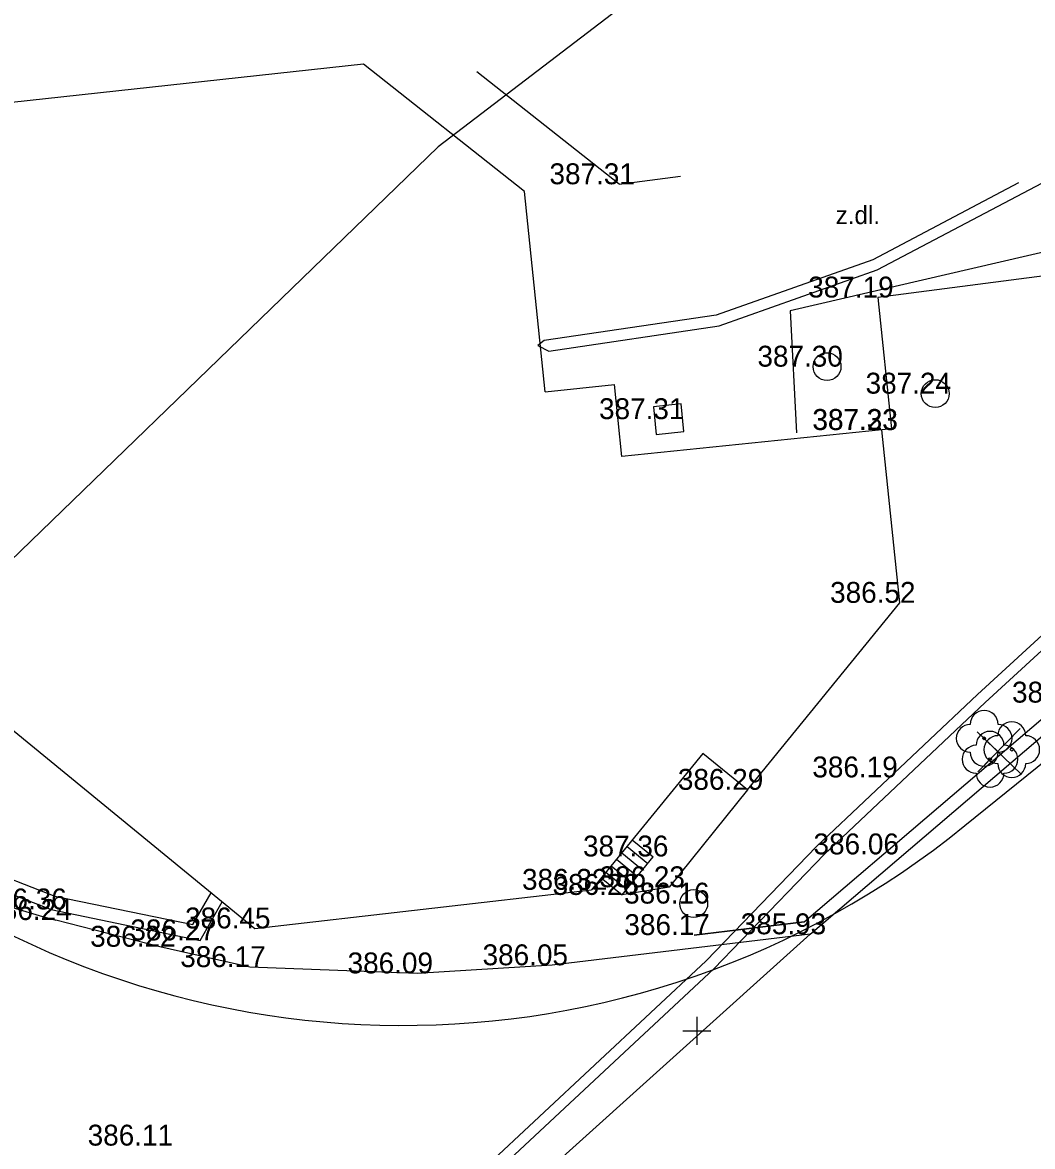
# Model space of a CAD drawing. Extents: x -438233 to -437334, y -1133133 to -1132623.
# Drawn here: x -438124.22 to -438087.94, y -1132954.16 to -1132913.79 of the extents above; entities that cross this region are included whole.
import ezdxf

# ---------------------------------------------------------------- set-up
doc = ezdxf.new("R2010")
doc.units = 0
for name, color, linetype in [('Vrstva 1', 7, 'Continuous'), ('Vrstva 10', 7, 'Continuous'), ('Vrstva 11', 7, 'Continuous'), ('Vrstva 22', 7, 'Continuous'), ('Vrstva 26', 7, 'Continuous'), ('Vrstva 27', 7, 'Continuous'), ('Vrstva 3', 7, 'Continuous'), ('Vrstva 40', 7, 'Continuous'), ('Vrstva 5', 7, 'Continuous'), ('Vrstva 52', 7, 'Continuous'), ('Vrstva 54', 7, 'Continuous'), ('Vrstva 55', 7, 'Continuous'), ('Vrstva 61', 7, 'Continuous'), ('Vrstva 7', 7, 'Continuous'), ('Vrstva 9', 7, 'Continuous')]:
    doc.layers.add(name, color=color, linetype=linetype)

msp = doc.modelspace()

# ---------------------------------------------------------------- linework, layer by layer
at = {"layer": 'Vrstva 1'}
for p, q in [((-438111.968, -1132915.287), (-438111.968, -1132915.287)), ((-438106.192, -1132919.855), (-438106.192, -1132919.855)), ((-438102.793, -1132919.6), (-438102.793, -1132919.6)), ((-438093.499, -1132923.668), (-438093.499, -1132923.668)), ((-438095.324, -1132926.15), (-438095.324, -1132926.15)), ((-438102.958, -1132926.794), (-438102.958, -1132926.794)), ((-438091.439, -1132927.119), (-438091.439, -1132927.119)), ((-438101.013, -1132928.035), (-438101.013, -1132928.035)), ((-438093.353, -1132928.422), (-438093.353, -1132928.422)), ((-438093.344, -1132928.427), (-438093.344, -1132928.427)), ((-438090.373, -1132942.634), (-438074.748, -1132930.004)), ((-438092.714, -1132934.632), (-438092.714, -1132934.632)), ((-438093.352, -1132940.901), (-438093.352, -1132940.901)), ((-438098.181, -1132941.346), (-438098.181, -1132941.346)), ((-438101.588, -1132943.74), (-438101.588, -1132943.74)), ((-438093.309, -1132943.665), (-438093.309, -1132943.665)), ((-438103.779, -1132944.937), (-438103.779, -1132944.937)), ((-438100.997, -1132944.845), (-438100.997, -1132944.845)), ((-438102.682, -1132945.121), (-438102.682, -1132945.121)), ((-438123.197, -1132945.641), (-438123.197, -1132945.641)), ((-438100.113, -1132945.432), (-438100.113, -1132945.432)), ((-438123.021, -1132946.022), (-438123.021, -1132946.022)), ((-438115.881, -1132946.325), (-438115.881, -1132946.325)), ((-438100.102, -1132946.562), (-438100.102, -1132946.562)), ((-438095.924, -1132946.534), (-438095.924, -1132946.534)), ((-438119.29, -1132946.982), (-438119.29, -1132946.982)), ((-438117.845, -1132946.752), (-438117.845, -1132946.752)), ((-438116.055, -1132947.713), (-438116.055, -1132947.713)), ((-438105.196, -1132947.647), (-438105.196, -1132947.647)), ((-438110.044, -1132947.938), (-438110.044, -1132947.938)), ((-438119.38, -1132954.123), (-438119.38, -1132954.123))]:
    msp.add_line(p, q, dxfattribs=at)
msp.add_arc((-438110.563, -1132917.807), 32, 230.3365, 309.1186, dxfattribs=at)
at = {"layer": 'Vrstva 10'}
msp.add_line((-438095.924, -1132946.534), (-438114.084, -1132962.853), dxfattribs=at)
for points in [[(-438095.924, -1132946.534), (-438086.179, -1132938.215), (-438074.983, -1132928.454)], [(-438095.924, -1132946.534), (-438105.196, -1132947.647), (-438110.044, -1132947.938), (-438116.055, -1132947.713), (-438119.29, -1132946.982), (-438123.021, -1132946.022)]]:
    msp.add_lwpolyline(points, dxfattribs=at)
msp.add_arc((-438115.759, -1132917.821), 29.121, 239.8641, 255.5591, dxfattribs=at)
at = {"layer": 'Vrstva 11'}
for p, q in [((-438102.508, -1132943.378), (-438101.759, -1132943.988)), ((-438102.319, -1132943.145), (-438101.57, -1132943.755)), ((-438102.698, -1132943.61), (-438101.949, -1132944.22)), ((-438103.077, -1132944.075), (-438102.328, -1132944.685)), ((-438102.887, -1132943.843), (-438102.138, -1132944.453)), ((-438103.431, -1132944.511), (-438102.682, -1132945.121)), ((-438103.266, -1132944.308), (-438102.517, -1132944.918))]:
    msp.add_line(p, q, dxfattribs=at)
for points in [[(-438102.793, -1132919.6), (-438107.901, -1132915.561)], [(-438102.793, -1132919.6), (-438100.584, -1132919.31)], [(-438080.604, -1132921.986), (-438093.499, -1132923.668), (-438093.013, -1132928.387), (-438093.353, -1132928.422)], [(-438098.181, -1132941.346), (-438100.997, -1132944.845), (-438102.682, -1132945.121)], [(-438102.682, -1132945.121), (-438101.57, -1132943.755)]]:
    msp.add_lwpolyline(points, dxfattribs=at)
at = {"layer": 'Vrstva 22'}
for centre in [(-438089.68, -1132939.498), (-438088.688, -1132939.904), (-438089.469, -1132940.248)]:
    msp.add_circle(centre, 0.05, dxfattribs=at)
for centre, start, end in [((-438089.68, -1132938.998), 0, 180), ((-438088.688, -1132939.404), 0, 180), ((-438090.18, -1132939.498), 90, 270), ((-438089.469, -1132939.748), 0, 180), ((-438089.18, -1132939.498), 270, 90), ((-438089.969, -1132940.248), 90, 270), ((-438089.188, -1132939.904), 90, 270), ((-438088.969, -1132940.248), 270, 90), ((-438088.188, -1132939.904), 270, 90), ((-438089.68, -1132939.998), 180, 0), ((-438088.688, -1132940.404), 180, 0), ((-438089.469, -1132940.748), 180, 0)]:
    msp.add_arc(centre, 0.5, start, end, dxfattribs=at)
at = {"layer": 'Vrstva 26'}
msp.add_lwpolyline([(-438100.567, -1132927.486), (-438101.562, -1132927.589), (-438101.459, -1132928.584), (-438100.464, -1132928.481)], close=True, dxfattribs=at)
at = {"layer": 'Vrstva 27'}
for centre in [(-438095.324, -1132926.15), (-438091.439, -1132927.119), (-438100.113, -1132945.432)]:
    msp.add_circle(centre, 0.5, dxfattribs=at)
at = {"layer": 'Vrstva 40'}
msp.add_lwpolyline([(-438088.386, -1132939.139), (-438089.906, -1132940.705), (-438089.195, -1132939.972), (-438089.928, -1132939.261), (-438088.356, -1132940.787)], dxfattribs=at)
at = {"layer": 'Vrstva 5'}
for p, q in [((-438105.451, -1132927.051), (-438106.192, -1132919.855)), ((-438105.451, -1132927.051), (-438102.958, -1132926.794)), ((-438102.691, -1132929.383), (-438102.958, -1132926.794)), ((-438093.353, -1132928.422), (-438102.691, -1132929.383)), ((-438092.714, -1132934.632), (-438093.353, -1132928.422)), ((-438098.181, -1132941.346), (-438092.714, -1132934.632)), ((-438125.927, -1132938.095), (-438115.881, -1132946.325)), ((-438099.789, -1132940.037), (-438103.778, -1132944.938)), ((-438098.181, -1132941.346), (-438099.789, -1132940.037)), ((-438115.881, -1132946.325), (-438103.779, -1132944.937))]:
    msp.add_line(p, q, dxfattribs=at)
for points in [[(-438111.968, -1132915.287), (-438125.93, -1132916.81), (-438130.7, -1132922.46)], [(-438106.192, -1132919.855), (-438111.968, -1132915.287)]]:
    msp.add_lwpolyline(points, dxfattribs=at)
at = {"layer": 'Vrstva 52'}
for points in [[(-438128.855, -1132990.779), (-438128.856, -1132990.91), (-438128.989, -1132990.91), (-438128.989, -1132990.659), (-438128.93, -1132990.596), (-438129.59, -1132987.39), (-438128.59, -1132984.69), (-438123.607, -1132978.703), (-438122.927, -1132977.811), (-438122.184, -1132976.902), (-438122.789, -1132976.078), (-438121.848, -1132973.845), (-438121.368, -1132972.611), (-438119.619, -1132967.617), (-438116.421, -1132963.158), (-438109.667, -1132956.824), (-438099.67, -1132947.487), (-438095.701, -1132943.378), (-438089.916, -1132937.924), (-438083.958, -1132932.455), (-438080.074, -1132928.641), (-438079.488, -1132927.786), (-438078.793, -1132926.015), (-438077.623, -1132919.546)], [(-438077.217, -1132919.546), (-438078.406, -1132926.125), (-438079.132, -1132927.975), (-438079.766, -1132928.899), (-438083.683, -1132932.745), (-438089.644, -1132938.217), (-438095.42, -1132943.663), (-438099.389, -1132947.772), (-438109.394, -1132957.116), (-438116.119, -1132963.423), (-438119.26, -1132967.803), (-438120.993, -1132972.75), (-438122.088, -1132975.591), (-438122.213, -1132976.074), (-438122.355, -1132976.074), (-438122.355, -1132975.945)], [(-438105.714, -1132925.389), (-438105.318, -1132925.591), (-438099.203, -1132924.69), (-438093.519, -1132922.677), (-438087.585, -1132919.546)], [(-438088.442, -1132919.546), (-438093.68, -1132922.31), (-438099.3, -1132924.3), (-438105.48, -1132925.21), (-438105.714, -1132925.389)]]:
    msp.add_lwpolyline(points, dxfattribs=at)
at = {"layer": 'Vrstva 54'}
msp.add_lwpolyline([(-438076.815, -1132919.546), (-438096.648, -1132924.148), (-438096.423, -1132928.529)], dxfattribs=at)
at = {"layer": 'Vrstva 55'}
msp.add_lwpolyline([(-438100.584, -1132911.605), (-438109.29, -1132918.26), (-438129.93, -1132938.22), (-438146.51, -1132953.64)], dxfattribs=at)
at = {"layer": 'Vrstva 61'}
for p, q in [((-438100, -1132949.5), (-438100, -1132950.5)), ((-438100.5, -1132950), (-438099.5, -1132950))]:
    msp.add_line(p, q, dxfattribs=at)
at = {"layer": 'Vrstva 7'}
for points in [[(-438128.639, -1132940.673), (-438129.292, -1132943.274), (-438123.197, -1132945.641), (-438117.845, -1132946.752), (-438117.048, -1132945.369)], [(-438128.154, -1132940.795), (-438128.7, -1132942.968), (-438123.055, -1132945.16), (-438118.098, -1132946.189), (-438117.44, -1132945.048)]]:
    msp.add_lwpolyline(points, dxfattribs=at)
at = {"layer": 'Vrstva 9'}
for points in [[(-438100.102, -1132946.562), (-438096.145, -1132946.087), (-438086.495, -1132937.848), (-438075.407, -1132927.936)], [(-438096.145, -1132946.087), (-438100.102, -1132946.562)]]:
    msp.add_lwpolyline(points, dxfattribs=at)

# ---------------------------------------------------------------- texts
at = {"layer": 'Vrstva 3'}
for s, p in [('387.31 ', (-438105.293, -1132919.6)), ('387.19 ', (-438095.999, -1132923.668)), ('387.30 ', (-438097.824, -1132926.15)), ('387.24 ', (-438093.939, -1132927.119)), ('387.31 ', (-438103.513, -1132928.035)), ('387.33 ', (-438095.853, -1132928.422)), ('387.23 ', (-438095.844, -1132928.427)), ('386.52 ', (-438095.214, -1132934.632)), ('386.05 ', (-438088.679, -1132938.215)), ('386.19 ', (-438095.852, -1132940.901)), ('386.29 ', (-438100.681, -1132941.346)), ('387.36 ', (-438104.088, -1132943.74)), ('386.06 ', (-438095.809, -1132943.665)), ('386.32 ', (-438106.279, -1132944.937)), ('386.23 ', (-438103.497, -1132944.845)), ('386.26 ', (-438105.182, -1132945.121)), ('386.36 ', (-438125.697, -1132945.641)), ('386.16 ', (-438102.613, -1132945.432)), ('386.24 ', (-438125.521, -1132946.022)), ('386.45 ', (-438118.381, -1132946.325)), ('386.17 ', (-438102.602, -1132946.562)), ('385.93 ', (-438098.424, -1132946.534)), ('386.22 ', (-438121.79, -1132946.982)), ('386.27 ', (-438120.345, -1132946.752)), ('386.17 ', (-438118.555, -1132947.713)), ('386.05 ', (-438107.696, -1132947.647)), ('386.09 ', (-438112.544, -1132947.938)), ('386.11 ', (-438121.88, -1132954.123))]:
    msp.add_text(s, height=0.75, dxfattribs=at).set_placement(p)
at = {"layer": 'Vrstva 40'}
msp.add_text('z.dl.', height=0.65, dxfattribs=at).set_placement((-438095.015, -1132921.031))

doc.saveas('drawing.dxf')
